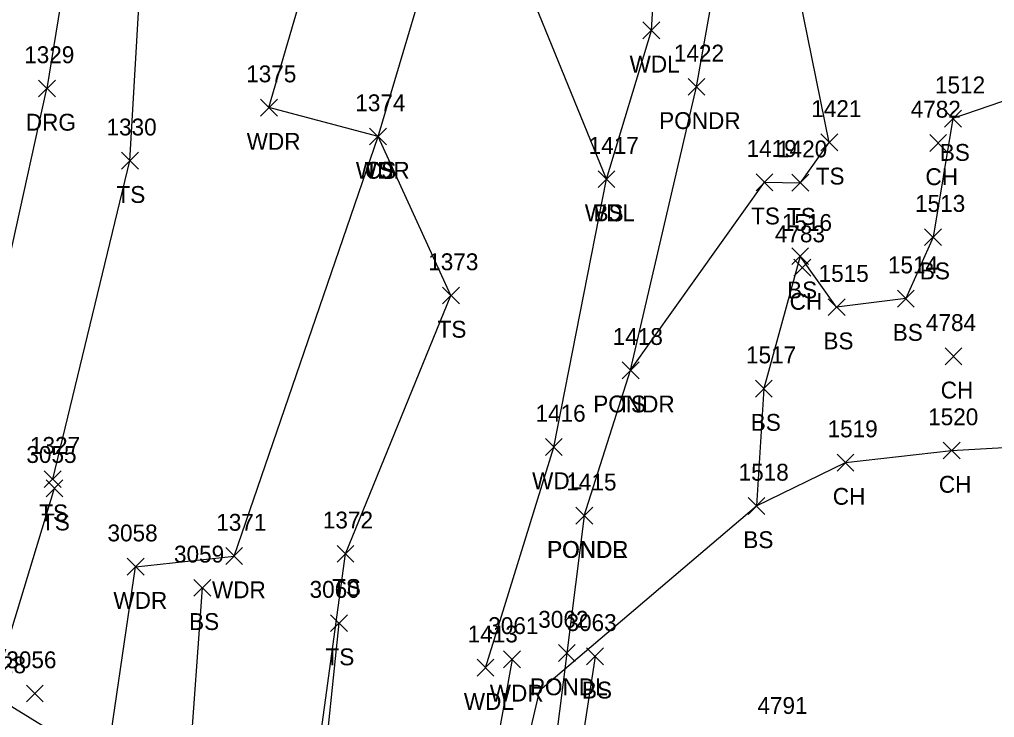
# Model space of a CAD drawing. Extents: x 49137 to 50946, y 9590 to 10709.
# Drawn here: x 50061.8 to 50177.5, y 9806.1 to 9888.9 of the extents above; entities that cross this region are included whole.
import ezdxf

# ---------------------------------------------------------------- set-up
doc = ezdxf.new("R2010")
doc.units = 0
for name, color, linetype in [('D_I', 7, 'Continuous'), ('D_TIC', 7, 'Continuous'), ('DCP', 7, 'Continuous'), ('L_A', 7, 'Continuous'), ('L_I', 7, 'Continuous'), ('L_TIC', 7, 'Continuous'), ('LAWA', 7, 'Continuous'), ('LAWE', 7, 'Continuous'), ('LELB', 7, 'Continuous'), ('LSOGP', 7, 'Continuous'), ('R_A', 7, 'Continuous'), ('R_I', 7, 'Continuous'), ('R_TIC', 7, 'Continuous'), ('RDG', 7, 'Continuous')]:
    doc.layers.add(name, color=color, linetype=linetype)

msp = doc.modelspace()

# ---------------------------------------------------------------- linework, layer by layer
at = {"layer": 'D_TIC'}
for points in [[(50062.64, 9807.97), (50064.64, 9809.97)], [(50064.64, 9807.97), (50062.64, 9809.97)]]:
    msp.add_lwpolyline(points, dxfattribs=at)
at = {"layer": 'DCP'}
msp.add_lwpolyline([(49941.69, 9827.48), (50059.34, 9808.37), (50181.4, 9733.09), (50281.74, 9743.29), (50422.72, 9892.52), (50122.34, 10663.61), (50179.93, 10552.61), (50179.64, 10394.45), (50122.34, 10285.07), (50121.56, 10284.35)], dxfattribs=at)
at = {"layer": 'L_TIC'}
for points in [[(50135.76, 9886.6), (50137.76, 9888.6)], [(50137.76, 9886.6), (50135.76, 9888.6)], [(50141.11, 9879.9), (50143.11, 9881.9)], [(50143.11, 9879.9), (50141.11, 9881.9)], [(50090.4, 9877.44), (50092.4, 9879.44)], [(50092.4, 9877.44), (50090.4, 9879.44)], [(50171.52, 9876.13), (50173.52, 9878.13)], [(50173.52, 9876.13), (50171.52, 9878.13)], [(50103.34, 9874.01), (50105.34, 9876.01)], [(50105.34, 9874.01), (50103.34, 9876.01)], [(50103.34, 9874.01), (50105.34, 9876.01)], [(50105.34, 9874.01), (50103.34, 9876.01)], [(50103.34, 9874.01), (50105.34, 9876.01)], [(50105.34, 9874.01), (50103.34, 9876.01)], [(50156.85, 9873.32), (50158.85, 9875.32)], [(50158.85, 9873.32), (50156.85, 9875.32)], [(50169.77, 9873.25), (50171.77, 9875.25)], [(50171.77, 9873.25), (50169.77, 9875.25)], [(50073.91, 9871.14), (50075.91, 9873.14)], [(50075.91, 9871.14), (50073.91, 9873.14)], [(50130.44, 9868.96), (50132.44, 9870.96)], [(50132.44, 9868.96), (50130.44, 9870.96)], [(50130.44, 9868.96), (50132.44, 9870.96)], [(50132.44, 9868.96), (50130.44, 9870.96)], [(50149.17, 9868.59), (50151.17, 9870.59)], [(50151.17, 9868.59), (50149.17, 9870.59)], [(50153.43, 9868.54), (50155.43, 9870.54)], [(50155.43, 9868.54), (50153.43, 9870.54)], [(50169.16, 9862.08), (50171.16, 9864.08)], [(50171.16, 9862.08), (50169.16, 9864.08)], [(50153.41, 9859.82), (50155.41, 9861.82)], [(50155.41, 9859.82), (50153.41, 9861.82)], [(50153.66, 9858.47), (50155.66, 9860.47)], [(50155.66, 9858.47), (50153.66, 9860.47)], [(50111.99, 9855.16), (50113.99, 9857.16)], [(50113.99, 9855.16), (50111.99, 9857.16)], [(50165.94, 9854.79), (50167.94, 9856.79)], [(50167.94, 9854.79), (50165.94, 9856.79)], [(50157.72, 9853.78), (50159.72, 9855.78)], [(50159.72, 9853.78), (50157.72, 9855.78)], [(50171.58, 9847.95), (50173.58, 9849.95)], [(50173.58, 9847.95), (50171.58, 9849.95)], [(50133.29, 9846.3), (50135.29, 9848.3)], [(50135.29, 9846.3), (50133.29, 9848.3)], [(50133.29, 9846.3), (50135.29, 9848.3)], [(50135.29, 9846.3), (50133.29, 9848.3)], [(50149.1, 9844.12), (50151.1, 9846.12)], [(50151.1, 9844.12), (50149.1, 9846.12)], [(50124.19, 9837.2), (50126.19, 9839.2)], [(50126.19, 9837.2), (50124.19, 9839.2)], [(50171.36, 9836.78), (50173.36, 9838.78)], [(50173.36, 9836.78), (50171.36, 9838.78)], [(50158.78, 9835.35), (50160.78, 9837.35)], [(50160.78, 9835.35), (50158.78, 9837.35)], [(50064.75, 9833.39), (50066.75, 9835.39)], [(50066.75, 9833.39), (50064.75, 9835.39)], [(50064.96, 9832.31), (50066.96, 9834.31)], [(50066.96, 9832.31), (50064.96, 9834.31)], [(50148.22, 9830.21), (50150.22, 9832.21)], [(50150.22, 9830.21), (50148.22, 9832.21)], [(50127.8, 9829.05), (50129.8, 9831.05)], [(50129.8, 9829.05), (50127.8, 9831.05)], [(50127.8, 9829.05), (50129.8, 9831.05)], [(50129.8, 9829.05), (50127.8, 9831.05)], [(50086.28, 9824.27), (50088.28, 9826.27)], [(50088.28, 9824.27), (50086.28, 9826.27)], [(50099.48, 9824.54), (50101.48, 9826.54)], [(50101.48, 9824.54), (50099.48, 9826.54)], [(50074.59, 9823.01), (50076.59, 9825.01)], [(50076.59, 9823.01), (50074.59, 9825.01)], [(50082.49, 9820.5), (50084.49, 9822.5)], [(50084.49, 9820.5), (50082.49, 9822.5)], [(50098.7, 9816.32), (50100.7, 9818.32)], [(50100.7, 9816.32), (50098.7, 9818.32)], [(50119.23, 9812.02), (50121.23, 9814.02)], [(50121.23, 9812.02), (50119.23, 9814.02)], [(50125.73, 9812.77), (50127.73, 9814.77)], [(50127.73, 9812.77), (50125.73, 9814.77)], [(50129.08, 9812.38), (50131.08, 9814.38)], [(50131.08, 9812.38), (50129.08, 9814.38)], [(50116.09, 9811.03), (50118.09, 9813.03)], [(50118.09, 9811.03), (50116.09, 9813.03)]]:
    msp.add_lwpolyline(points, dxfattribs=at)
at = {"layer": 'LAWA'}
for points in [[(50117.09, 9812.03), (50125.19, 9838.2), (50131.44, 9869.96), (50136.76, 9887.6), (50137.75, 9904.59), (50153.56, 9910.03), (50161.77, 9913.05), (50163.42, 9912.91), (50169.87, 9921.06), (50171.08, 9921.49), (50182.45, 9921.95), (50191.92, 9928.44), (50180.6, 9949.5), (50171.66, 9967.48), (50163.03, 9983.02), (50150.28, 9995.84), (50140.4, 9991.18), (50131.52, 9978.47)], [(50087.28, 9825.27), (50104.34, 9875.01), (50091.4, 9878.44), (50099.17, 9905.12), (50109.21, 9926.25), (50123.9, 9936.53), (50125.34, 9938.06), (50126.2, 9942.93), (50130.79, 9959.09), (50131.36, 9973.37), (50131.52, 9978.47)], [(50075.59, 9824.01), (50087.28, 9825.27)], [(50014.58, 9702.26), (50036.88, 9735.4), (50049.69, 9755.98), (50071.14, 9793.79), (50075.59, 9824.01)], [(50120.23, 9813.02), (50117.45, 9797.5), (50106.28, 9771.82), (50106.85, 9750.63), (50099.47, 9727.17), (50099.61, 9719.17), (50096.85, 9701.02)]]:
    msp.add_lwpolyline(points, dxfattribs=at)
at = {"layer": 'LAWE'}
for points in [[(50128.8, 9830.05), (50134.29, 9847.3), (50142.11, 9880.9), (50145.47, 9899.84), (50152.79, 9899.24), (50158.84, 9904.9), (50168.73, 9907.32), (50170.14, 9900.19), (50173.37, 9900.16), (50184.59, 9903.76), (50198.34, 9914.07), (50214.56, 9902.92), (50226.92, 9887.06)], [(50126.73, 9813.77), (50124.61, 9796.89), (50111.25, 9777.04), (50110.47, 9750.09), (50103.82, 9729.7), (50104.43, 9724.64), (50098.48, 9698.71), (50117.09, 9681.54), (50135.81, 9695.39), (50163.01, 9717.6), (50180.53, 9734.32), (50190.61, 9745.36), (50201.6, 9744.39), (50218.67, 9763.18), (50226.18, 9771.82), (50238.61, 9779.61), (50252.96, 9798.03), (50263.09, 9822.8), (50257.66, 9841.25), (50250.32, 9860.86)], [(50128.8, 9830.05), (50126.73, 9813.77)]]:
    msp.add_lwpolyline(points, dxfattribs=at)
at = {"layer": 'LELB'}
for points in [[(50065.75, 9834.39), (50074.91, 9872.14), (50076.24, 9895.19), (50081.29, 9914.45), (50087.86, 9934.32), (50097.47, 9943.81), (50111.57, 9942.27)], [(50131.44, 9869.96), (50121.55, 9894.2), (50128.84, 9904.54), (50137.75, 9904.59), (50140.3, 9923.19), (50138.53, 9928.68), (50138.54, 9928.9), (50144, 9935.71)], [(50104.34, 9875.01), (50112.36, 9902), (50129.8, 9920.06)], [(50214.56, 9902.92), (50198.38, 9885.99), (50172.52, 9877.13), (50170.16, 9863.08), (50166.94, 9855.79), (50158.72, 9854.78), (50154.41, 9860.82), (50150.1, 9845.12), (50149.22, 9831.21)], [(50134.29, 9847.3), (50150.17, 9869.59), (50154.43, 9869.54), (50157.85, 9874.32), (50152.79, 9899.24)], [(50090.63, 9783.84), (50096.35, 9795.46), (50100.48, 9825.54), (50112.99, 9856.16), (50104.34, 9875.01)], [(50130.08, 9813.38), (50127.49, 9796.45), (50115.24, 9773.32), (50112.63, 9748.12), (50107.86, 9731.67), (50105.33, 9723.23), (50101.67, 9703.92), (50120.36, 9686.99), (50133.96, 9697.22), (50159.53, 9719.77), (50180.67, 9741.2), (50186.56, 9749.96), (50198.54, 9748.57), (50219.91, 9767.49), (50235.59, 9782.92), (50251.48, 9801.83), (50259.82, 9821.36), (50255.17, 9839.31), (50246.31, 9858.9)], [(49918.74, 9626.48), (49955.93, 9659.04), (50003.73, 9703.66), (50024.34, 9743.65), (50032.96, 9768.3), (50056.89, 9803.49), (50065.96, 9833.31)], [(50083.49, 9821.5), (50081.95, 9800.15), (50073.64, 9774.41), (50064.64, 9762.89), (50058.78, 9735.45), (50049.82, 9711.33), (50039.25, 9694.43), (50032.02, 9676.72), (50013.68, 9661.38), (49987.38, 9644.23), (49938.8, 9613.7)], [(50099.7, 9817.32), (50097.66, 9797.85), (50091.08, 9768.66), (50091.51, 9751.39), (50093.9, 9729.47), (50092.55, 9720), (50088.42, 9676.7)]]:
    msp.add_lwpolyline(points, dxfattribs=at)
at = {"layer": 'LSOGP'}
msp.add_lwpolyline([(49755.15, 9779.76), (49800.92, 9796.37), (49846.88, 9798.73), (49883.29, 9814.53), (49941.82, 9793.29), (49953.02, 9787.37), (49967.5, 9785.27), (49973.48, 9780.68), (49984.2, 9774.21), (50003.83, 9766.28), (50024.54, 9762.42), (50047.5, 9786.77), (50075.33, 9785.18), (50090.63, 9783.84), (50104.73, 9771.51), (50112.8, 9763.41), (50118.43, 9787.61), (50123.54, 9809.37), (50149.22, 9831.22), (50159.79, 9836.35), (50172.36, 9837.78), (50185.48, 9838.52)], dxfattribs=at)
at = {"layer": 'R_TIC'}
for points in [[(50064.07, 9879.71), (50066.07, 9881.71)], [(50066.07, 9879.71), (50064.07, 9881.71)], [(50064.07, 9879.71), (50066.07, 9881.71)], [(50066.07, 9879.71), (50064.07, 9881.71)]]:
    msp.add_lwpolyline(points, dxfattribs=at)
at = {"layer": 'RDG'}
for points in [[(49989.55, 9915.93), (50001.07, 9909.43), (50013.31, 9906.77), (50039.56, 9915.6), (50071.42, 9919.88), (50065.07, 9880.71)], [(50056.89, 9843.71), (50065.07, 9880.71)]]:
    msp.add_lwpolyline(points, dxfattribs=at)

# ---------------------------------------------------------------- texts
at = {"layer": 'D_I'}
for s, p in [('3056', (50060.25, 9811.97)), ('1328', (50056.64, 9811.37))]:
    msp.add_text(s, height=2, dxfattribs=at).set_placement(p)
at = {"layer": 'L_A'}
for s, p in [('WDL', (50134.17, 9882.6)), ('PONDR', (50137.68, 9875.9)), ('WDR', (50088.76, 9873.44)), ('BS', (50170.96, 9872.13)), ('WDR', (50101.7, 9870.01)), ('TS', (50102.75, 9870.01)), ('CS', (50102.78, 9870.01)), ('TS', (50156.25, 9869.32)), ('CH', (50169.26, 9869.25)), ('TS', (50073.32, 9867.14)), ('WDL', (50128.86, 9864.96)), ('BS', (50129.89, 9864.96)), ('TS', (50148.58, 9864.59)), ('TS', (50152.84, 9864.54)), ('BS', (50168.6, 9858.08)), ('BS', (50152.85, 9855.82)), ('CH', (50153.15, 9854.47)), ('TS', (50111.4, 9851.16)), ('BS', (50165.38, 9850.79)), ('BS', (50157.16, 9849.78)), ('CH', (50171.07, 9843.95)), ('PONDR', (50129.86, 9842.3)), ('TS', (50132.7, 9842.3)), ('BS', (50148.54, 9840.12)), ('WDL', (50122.61, 9833.2)), ('CH', (50170.85, 9832.78)), ('CH', (50158.27, 9831.35)), ('TS', (50064.16, 9829.39)), ('TS', (50064.37, 9828.31)), ('BS', (50147.66, 9826.21)), ('PONDR', (50124.37, 9825.05)), ('PONDL', (50124.42, 9825.05)), ('WDR', (50084.64, 9820.27)), ('TS', (50098.89, 9820.54)), ('WDR', (50072.95, 9819.01)), ('BS', (50081.93, 9816.5)), ('TS', (50098.11, 9812.32)), ('PONDL', (50122.35, 9808.77)), ('WDR', (50117.59, 9808.02)), ('BS', (50128.52, 9808.38)), ('WDL', (50114.51, 9807.03))]:
    msp.add_text(s, height=2, dxfattribs=at).set_placement(p)
at = {"layer": 'L_I'}
for s, p in [('1422', (50139.42, 9883.9)), ('1375', (50088.7, 9881.44)), ('1512', (50170.39, 9880.13)), ('1374', (50101.64, 9878.01)), ('1374', (50101.64, 9878.01)), ('1374', (50101.64, 9878.01)), ('1421', (50155.72, 9877.32)), ('4782', (50167.51, 9877.25)), ('1330', (50072.13, 9875.14)), ('1417', (50129.32, 9872.96)), ('1417', (50129.32, 9872.96)), ('1419', (50148.04, 9872.59)), ('1420', (50151.66, 9872.54)), ('1513', (50168.03, 9866.08)), ('1516', (50152.23, 9863.82)), ('4783', (50151.4, 9862.47)), ('1373', (50110.29, 9859.16)), ('1514', (50164.81, 9858.79)), ('1515', (50156.59, 9857.78)), ('4784', (50169.32, 9851.95)), ('1418', (50132.17, 9850.3)), ('1418', (50132.17, 9850.3)), ('1517', (50147.98, 9848.12)), ('1416', (50123.01, 9841.2)), ('1520', (50169.58, 9840.78)), ('1519', (50157.65, 9839.35)), ('1327', (50063.06, 9837.39)), ('3055', (50062.63, 9836.31)), ('1518', (50147.1, 9834.21)), ('1415', (50126.67, 9833.05)), ('1415', (50126.67, 9833.05)), ('1371', (50085.15, 9828.27)), ('1372', (50097.79, 9828.54)), ('3058', (50072.25, 9827.01)), ('3059', (50080.14, 9824.5)), ('3060', (50096.22, 9820.32)), ('3062', (50123.34, 9816.77)), ('3061', (50117.41, 9816.02)), ('3063', (50126.69, 9816.38)), ('1413', (50114.97, 9815.03)), ('4791', (50149.33, 9806.55))]:
    msp.add_text(s, height=2, dxfattribs=at).set_placement(p)
at = {"layer": 'R_A'}
msp.add_text('DRG', height=2, dxfattribs=at).set_placement((50062.56, 9875.71))
msp.add_text('DRG', height=2, dxfattribs=at).set_placement((50062.56, 9875.71))
at = {"layer": 'R_I'}
msp.add_text('1329', height=2, dxfattribs=at).set_placement((50062.37, 9883.71))
msp.add_text('1329', height=2, dxfattribs=at).set_placement((50062.37, 9883.71))

doc.saveas('drawing.dxf')
